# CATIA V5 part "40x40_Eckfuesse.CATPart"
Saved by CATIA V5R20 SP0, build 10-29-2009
Part number: 40x40_Eckfuesse
Nomenclature: P40L_N8_I
Source: Unknown
Bounding box of the stored display mesh (mm): x -20 to 20, y -20 to 20, z -150 to 180
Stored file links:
  C:\Users\Andi\Desktop\Offene Projekte\Plasmacutter\Rahmen\40x40_Eckfuesse.CATPart
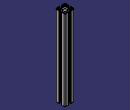
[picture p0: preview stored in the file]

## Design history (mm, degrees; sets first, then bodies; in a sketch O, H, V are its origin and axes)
Set1
  Sketch1 on face of Solid1, origin (0, 0, 150), H (1, 0, 0), V (0, 1, 0)
    projected arc E1 centre (-18.5, 5.5) radius 1.5 from (-20, 5.5) to (-18.5, 4) ccw from edge [face of Solid1 | face of Solid1]
    projected line E2 (-16.5, 4) -> (-18.5, 4) from edge [face of Solid1 | face of Solid1]
    projected arc E3 centre (-16.5, 5) radius 1 from (-16.5, 4) to (-15.5, 5) ccw from edge [face of Solid1 | face of Solid1]
    projected line E4 (-15.5, 6.5) -> (-15.5, 5) from edge [face of Solid1 | face of Solid1]
    projected arc E5 centre (-16, 6.5) radius 0.5 from (-15.5, 6.5) to (-16, 7) ccw from edge [face of Solid1 | face of Solid1]
    projected line E6 (-17.5, 7) -> (-16, 7) from edge [face of Solid1 | face of Solid1]
    projected arc E7 centre (-17.5, 7.5) radius 0.5 from (-18, 7.5) to (-17.5, 7) ccw from edge [face of Solid1 | face of Solid1]
    projected arc E8 centre (-15.5, 7.5) radius 2.5 from (-15.5, 10) to (-18, 7.5) ccw from edge [face of Solid1 | face of Solid1]
    projected line E9 (-14.1924, 10) -> (-15.5, 10) from edge [face of Solid1 | face of Solid1]
    projected arc E10 centre (-14.1924, 5) radius 5 from (-10.6569, 8.5355) to (-14.1924, 10) ccw from edge [face of Solid1 | face of Solid1]
    projected line E11 (-9.2145, 7.0931) -> (-10.6569, 8.5355) from edge [face of Solid1 | face of Solid1]
    projected arc E12 centre (-12.75, 3.5576) radius 5 from (-7.75, 3.5576) to (-9.2145, 7.0931) ccw from edge [face of Solid1 | face of Solid1]
    projected line E13 (-7.75, -3.5576) -> (-7.75, 3.5576) from edge [face of Solid1 | face of Solid1]
    projected arc E14 centre (-12.75, -3.5576) radius 5 from (-9.2145, -7.0931) to (-7.75, -3.5576) ccw from edge [face of Solid1 | face of Solid1]
    projected line E15 (-10.6569, -8.5355) -> (-9.2145, -7.0931) from edge [face of Solid1 | face of Solid1]
    projected arc E16 centre (-14.1924, -5) radius 5 from (-14.1924, -10) to (-10.6569, -8.5355) ccw from edge [face of Solid1 | face of Solid1]
    projected line E17 (-15.5, -10) -> (-14.1924, -10) from edge [face of Solid1 | face of Solid1]
    projected arc E18 centre (-15.5, -7.5) radius 2.5 from (-18, -7.5) to (-15.5, -10) ccw from edge [face of Solid1 | face of Solid1]
    projected arc E19 centre (-17.5, -7.5) radius 0.5 from (-17.5, -7) to (-18, -7.5) ccw from edge [face of Solid1 | face of Solid1]
    projected line E20 (-16, -7) -> (-17.5, -7) from edge [face of Solid1 | face of Solid1]
    projected arc E21 centre (-16, -6.5) radius 0.5 from (-16, -7) to (-15.5, -6.5) ccw from edge [face of Solid1 | face of Solid1]
    projected line E22 (-15.5, -5) -> (-15.5, -6.5) from edge [face of Solid1 | face of Solid1]
    projected arc E23 centre (-16.5, -5) radius 1 from (-15.5, -5) to (-16.5, -4) ccw from edge [face of Solid1 | face of Solid1]
    projected line E24 (-18.5, -4) -> (-16.5, -4) from edge [face of Solid1 | face of Solid1]
    projected arc E25 centre (-18.5, -5.5) radius 1.5 from (-18.5, -4) to (-20, -5.5) ccw from edge [face of Solid1 | face of Solid1]
    projected line E26 (-20, -16) -> (-20, -5.5) from edge [face of Solid1 | face of Solid1]
    projected arc E27 centre (-16, -16) radius 4 from (-20, -16) to (-16, -20) ccw from edge [face of Solid1 | face of Solid1]
    projected line E28 (-5.5, -20) -> (-16, -20) from edge [face of Solid1 | face of Solid1]
    projected arc E29 centre (-5.5, -18.5) radius 1.5 from (-5.5, -20) to (-4, -18.5) ccw from edge [face of Solid1 | face of Solid1]
    projected line E30 (-4, -16.5) -> (-4, -18.5) from edge [face of Solid1 | face of Solid1]
    projected arc E31 centre (-5, -16.5) radius 1 from (-4, -16.5) to (-5, -15.5) ccw from edge [face of Solid1 | face of Solid1]
    projected line E32 (-6.5, -15.5) -> (-5, -15.5) from edge [face of Solid1 | face of Solid1]
    projected arc E33 centre (-6.5, -16) radius 0.5 from (-6.5, -15.5) to (-7, -16) ccw from edge [face of Solid1 | face of Solid1]
    projected line E34 (-7, -17.5) -> (-7, -16) from edge [face of Solid1 | face of Solid1]
    projected arc E35 centre (-7.5, -17.5) radius 0.5 from (-7.5, -18) to (-7, -17.5) ccw from edge [face of Solid1 | face of Solid1]
    projected arc E36 centre (-7.5, -15.5) radius 2.5 from (-10, -15.5) to (-7.5, -18) ccw from edge [face of Solid1 | face of Solid1]
    projected line E37 (-10, -14.1924) -> (-10, -15.5) from edge [face of Solid1 | face of Solid1]
    projected arc E38 centre (-5, -14.1924) radius 5 from (-8.5355, -10.6569) to (-10, -14.1924) ccw from edge [face of Solid1 | face of Solid1]
    projected line E39 (-7.0931, -9.2145) -> (-8.5355, -10.6569) from edge [face of Solid1 | face of Solid1]
    projected arc E40 centre (-3.5576, -12.75) radius 5 from (-3.5576, -7.75) to (-7.0931, -9.2145) ccw from edge [face of Solid1 | face of Solid1]
    projected line E41 (3.5576, -7.75) -> (-3.5576, -7.75) from edge [face of Solid1 | face of Solid1]
    projected arc E42 centre (3.5576, -12.75) radius 5 from (7.0931, -9.2145) to (3.5576, -7.75) ccw from edge [face of Solid1 | face of Solid1]
    projected line E43 (8.5355, -10.6569) -> (7.0931, -9.2145) from edge [face of Solid1 | face of Solid1]
    projected arc E44 centre (5, -14.1924) radius 5 from (10, -14.1924) to (8.5355, -10.6569) ccw from edge [face of Solid1 | face of Solid1]
    projected line E45 (10, -15.5) -> (10, -14.1924) from edge [face of Solid1 | face of Solid1]
    projected arc E46 centre (7.5, -15.5) radius 2.5 from (7.5, -18) to (10, -15.5) ccw from edge [face of Solid1 | face of Solid1]
    projected arc E47 centre (7.5, -17.5) radius 0.5 from (7, -17.5) to (7.5, -18) ccw from edge [face of Solid1 | face of Solid1]
    projected line E48 (7, -16) -> (7, -17.5) from edge [face of Solid1 | face of Solid1]
    projected arc E49 centre (6.5, -16) radius 0.5 from (7, -16) to (6.5, -15.5) ccw from edge [face of Solid1 | face of Solid1]
    projected line E50 (5, -15.5) -> (6.5, -15.5) from edge [face of Solid1 | face of Solid1]
    projected arc E51 centre (5, -16.5) radius 1 from (5, -15.5) to (4, -16.5) ccw from edge [face of Solid1 | face of Solid1]
    projected line E52 (4, -18.5) -> (4, -16.5) from edge [face of Solid1 | face of Solid1]
    projected arc E53 centre (5.5, -18.5) radius 1.5 from (4, -18.5) to (5.5, -20) ccw from edge [face of Solid1 | face of Solid1]
    projected line E54 (16, -20) -> (5.5, -20) from edge [face of Solid1 | face of Solid1]
    projected arc E55 centre (16, -16) radius 4 from (16, -20) to (20, -16) ccw from edge [face of Solid1 | face of Solid1]
    projected line E56 (20, -5.5) -> (20, -16) from edge [face of Solid1 | face of Solid1]
    projected arc E57 centre (18.5, -5.5) radius 1.5 from (20, -5.5) to (18.5, -4) ccw from edge [face of Solid1 | face of Solid1]
    projected line E58 (16.5, -4) -> (18.5, -4) from edge [face of Solid1 | face of Solid1]
    projected arc E59 centre (16.5, -5) radius 1 from (16.5, -4) to (15.5, -5) ccw from edge [face of Solid1 | face of Solid1]
    projected line E60 (15.5, -6.5) -> (15.5, -5) from edge [face of Solid1 | face of Solid1]
    projected arc E61 centre (16, -6.5) radius 0.5 from (15.5, -6.5) to (16, -7) ccw from edge [face of Solid1 | face of Solid1]
    projected line E62 (17.5, -7) -> (16, -7) from edge [face of Solid1 | face of Solid1]
    projected arc E63 centre (17.5, -7.5) radius 0.5 from (18, -7.5) to (17.5, -7) ccw from edge [face of Solid1 | face of Solid1]
    projected arc E64 centre (15.5, -7.5) radius 2.5 from (15.5, -10) to (18, -7.5) ccw from edge [face of Solid1 | face of Solid1]
    projected line E65 (14.1924, -10) -> (15.5, -10) from edge [face of Solid1 | face of Solid1]
    projected arc E66 centre (14.1924, -5) radius 5 from (10.6569, -8.5355) to (14.1924, -10) ccw from edge [face of Solid1 | face of Solid1]
    projected line E67 (9.2145, -7.0931) -> (10.6569, -8.5355) from edge [face of Solid1 | face of Solid1]
    projected arc E68 centre (12.75, -3.5576) radius 5 from (7.75, -3.5576) to (9.2145, -7.0931) ccw from edge [face of Solid1 | face of Solid1]
    projected line E69 (7.75, 3.5576) -> (7.75, -3.5576) from edge [face of Solid1 | face of Solid1]
    projected arc E70 centre (12.75, 3.5576) radius 5 from (9.2145, 7.0931) to (7.75, 3.5576) ccw from edge [face of Solid1 | face of Solid1]
    projected line E71 (10.6569, 8.5355) -> (9.2145, 7.0931) from edge [face of Solid1 | face of Solid1]
    projected arc E72 centre (14.1924, 5) radius 5 from (14.1924, 10) to (10.6569, 8.5355) ccw from edge [face of Solid1 | face of Solid1]
    projected line E73 (15.5, 10) -> (14.1924, 10) from edge [face of Solid1 | face of Solid1]
    projected arc E74 centre (15.5, 7.5) radius 2.5 from (18, 7.5) to (15.5, 10) ccw from edge [face of Solid1 | face of Solid1]
    projected arc E75 centre (17.5, 7.5) radius 0.5 from (17.5, 7) to (18, 7.5) ccw from edge [face of Solid1 | face of Solid1]
    projected line E76 (16, 7) -> (17.5, 7) from edge [face of Solid1 | face of Solid1]
    projected arc E77 centre (16, 6.5) radius 0.5 from (16, 7) to (15.5, 6.5) ccw from edge [face of Solid1 | face of Solid1]
    projected line E78 (15.5, 5) -> (15.5, 6.5) from edge [face of Solid1 | face of Solid1]
    projected arc E79 centre (16.5, 5) radius 1 from (15.5, 5) to (16.5, 4) ccw from edge [face of Solid1 | face of Solid1]
    projected line E80 (18.5, 4) -> (16.5, 4) from edge [face of Solid1 | face of Solid1]
    projected arc E81 centre (18.5, 5.5) radius 1.5 from (18.5, 4) to (20, 5.5) ccw from edge [face of Solid1 | face of Solid1]
    projected line E82 (20, 16) -> (20, 5.5) from edge [face of Solid1 | face of Solid1]
    projected arc E83 centre (16, 16) radius 4 from (20, 16) to (16, 20) ccw from edge [face of Solid1 | face of Solid1]
    projected line E84 (5.5, 20) -> (16, 20) from edge [face of Solid1 | face of Solid1]
    projected arc E85 centre (5.5, 18.5) radius 1.5 from (5.5, 20) to (4, 18.5) ccw from edge [face of Solid1 | face of Solid1]
    projected line E86 (4, 16.5) -> (4, 18.5) from edge [face of Solid1 | face of Solid1]
    projected arc E87 centre (5, 16.5) radius 1 from (4, 16.5) to (5, 15.5) ccw from edge [face of Solid1 | face of Solid1]
    projected line E88 (6.5, 15.5) -> (5, 15.5) from edge [face of Solid1 | face of Solid1]
    projected arc E89 centre (6.5, 16) radius 0.5 from (6.5, 15.5) to (7, 16) ccw from edge [face of Solid1 | face of Solid1]
    projected line E90 (7, 17.5) -> (7, 16) from edge [face of Solid1 | face of Solid1]
    projected arc E91 centre (7.5, 17.5) radius 0.5 from (7.5, 18) to (7, 17.5) ccw from edge [face of Solid1 | face of Solid1]
    projected arc E92 centre (7.5, 15.5) radius 2.5 from (10, 15.5) to (7.5, 18) ccw from edge [face of Solid1 | face of Solid1]
    projected line E93 (10, 14.1924) -> (10, 15.5) from edge [face of Solid1 | face of Solid1]
    projected arc E94 centre (5, 14.1924) radius 5 from (8.5355, 10.6569) to (10, 14.1924) ccw from edge [face of Solid1 | face of Solid1]
    projected line E95 (7.0931, 9.2145) -> (8.5355, 10.6569) from edge [face of Solid1 | face of Solid1]
    projected arc E96 centre (3.5576, 12.75) radius 5 from (3.5576, 7.75) to (7.0931, 9.2145) ccw from edge [face of Solid1 | face of Solid1]
    projected line E97 (-3.5576, 7.75) -> (3.5576, 7.75) from edge [face of Solid1 | face of Solid1]
    projected arc E98 centre (-3.5576, 12.75) radius 5 from (-7.0931, 9.2145) to (-3.5576, 7.75) ccw from edge [face of Solid1 | face of Solid1]
    projected line E99 (-8.5355, 10.6569) -> (-7.0931, 9.2145) from edge [face of Solid1 | face of Solid1]
    projected arc E100 centre (-5, 14.1924) radius 5 from (-10, 14.1924) to (-8.5355, 10.6569) ccw from edge [face of Solid1 | face of Solid1]
    projected line E101 (-10, 15.5) -> (-10, 14.1924) from edge [face of Solid1 | face of Solid1]
    projected arc E102 centre (-7.5, 15.5) radius 2.5 from (-7.5, 18) to (-10, 15.5) ccw from edge [face of Solid1 | face of Solid1]
    projected arc E103 centre (-7.5, 17.5) radius 0.5 from (-7, 17.5) to (-7.5, 18) ccw from edge [face of Solid1 | face of Solid1]
    projected line E104 (-7, 16) -> (-7, 17.5) from edge [face of Solid1 | face of Solid1]
    projected arc E105 centre (-6.5, 16) radius 0.5 from (-7, 16) to (-6.5, 15.5) ccw from edge [face of Solid1 | face of Solid1]
    projected line E106 (-5, 15.5) -> (-6.5, 15.5) from edge [face of Solid1 | face of Solid1]
    projected arc E107 centre (-5, 16.5) radius 1 from (-5, 15.5) to (-4, 16.5) ccw from edge [face of Solid1 | face of Solid1]
    projected line E108 (-4, 18.5) -> (-4, 16.5) from edge [face of Solid1 | face of Solid1]
    projected arc E109 centre (-5.5, 18.5) radius 1.5 from (-4, 18.5) to (-5.5, 20) ccw from edge [face of Solid1 | face of Solid1]
    projected line E110 (-16, 20) -> (-5.5, 20) from edge [face of Solid1 | face of Solid1]
    projected arc E111 centre (-16, 16) radius 4 from (-16, 20) to (-20, 16) ccw from edge [face of Solid1 | face of Solid1]
    projected line E112 (-20, 5.5) -> (-20, 16) from edge [face of Solid1 | face of Solid1]
    projected line E113 (11.8, -17.7) -> (11.8, -12.3) from edge [face of Solid1 | face of Solid1]
    projected arc E114 centre (12.3, -12.3) radius 0.5 from (12.3, -11.8) to (11.8, -12.3) ccw from edge [face of Solid1 | face of Solid1]
    projected line E115 (12.3, -11.8) -> (17.7, -11.8) from edge [face of Solid1 | face of Solid1]
    projected arc E116 centre (17.7, -12.3) radius 0.5 from (18.2, -12.3) to (17.7, -11.8) ccw from edge [face of Solid1 | face of Solid1]
    projected line E117 (18.2, -12.3) -> (18.2, -16) from edge [face of Solid1 | face of Solid1]
    projected arc E118 centre (16, -16) radius 2.2 from (16, -18.2) to (18.2, -16) ccw from edge [face of Solid1 | face of Solid1]
    projected line E119 (16, -18.2) -> (12.3, -18.2) from edge [face of Solid1 | face of Solid1]
    projected arc E120 centre (12.3, -17.7) radius 0.5 from (11.8, -17.7) to (12.3, -18.2) ccw from edge [face of Solid1 | face of Solid1]
    projected line E121 (-17.7, -11.8) -> (-12.3, -11.8) from edge [face of Solid1 | face of Solid1]
    projected arc E122 centre (-12.3, -12.3) radius 0.5 from (-11.8, -12.3) to (-12.3, -11.8) ccw from edge [face of Solid1 | face of Solid1]
    projected line E123 (-11.8, -12.3) -> (-11.8, -17.7) from edge [face of Solid1 | face of Solid1]
    projected arc E124 centre (-12.3, -17.7) radius 0.5 from (-12.3, -18.2) to (-11.8, -17.7) ccw from edge [face of Solid1 | face of Solid1]
    projected line E125 (-12.3, -18.2) -> (-16, -18.2) from edge [face of Solid1 | face of Solid1]
    projected arc E126 centre (-16, -16) radius 2.2 from (-18.2, -16) to (-16, -18.2) ccw from edge [face of Solid1 | face of Solid1]
    projected line E127 (-18.2, -16) -> (-18.2, -12.3) from edge [face of Solid1 | face of Solid1]
    projected arc E128 centre (-17.7, -12.3) radius 0.5 from (-17.7, -11.8) to (-18.2, -12.3) ccw from edge [face of Solid1 | face of Solid1]
    projected line E129 (-11.8, 17.7) -> (-11.8, 12.3) from edge [face of Solid1 | face of Solid1]
    projected arc E130 centre (-12.3, 12.3) radius 0.5 from (-12.3, 11.8) to (-11.8, 12.3) ccw from edge [face of Solid1 | face of Solid1]
    projected line E131 (-12.3, 11.8) -> (-17.7, 11.8) from edge [face of Solid1 | face of Solid1]
    projected arc E132 centre (-17.7, 12.3) radius 0.5 from (-18.2, 12.3) to (-17.7, 11.8) ccw from edge [face of Solid1 | face of Solid1]
    projected line E133 (-18.2, 12.3) -> (-18.2, 16) from edge [face of Solid1 | face of Solid1]
    projected arc E134 centre (-16, 16) radius 2.2 from (-16, 18.2) to (-18.2, 16) ccw from edge [face of Solid1 | face of Solid1]
    projected line E135 (-16, 18.2) -> (-12.3, 18.2) from edge [face of Solid1 | face of Solid1]
    projected arc E136 centre (-12.3, 17.7) radius 0.5 from (-11.8, 17.7) to (-12.3, 18.2) ccw from edge [face of Solid1 | face of Solid1]
    projected line E137 (17.7, 11.8) -> (12.3, 11.8) from edge [face of Solid1 | face of Solid1]
    projected arc E138 centre (12.3, 12.3) radius 0.5 from (11.8, 12.3) to (12.3, 11.8) ccw from edge [face of Solid1 | face of Solid1]
    projected line E139 (11.8, 12.3) -> (11.8, 17.7) from edge [face of Solid1 | face of Solid1]
    projected arc E140 centre (12.3, 17.7) radius 0.5 from (12.3, 18.2) to (11.8, 17.7) ccw from edge [face of Solid1 | face of Solid1]
    projected line E141 (12.3, 18.2) -> (16, 18.2) from edge [face of Solid1 | face of Solid1]
    projected arc E142 centre (16, 16) radius 2.2 from (18.2, 16) to (16, 18.2) ccw from edge [face of Solid1 | face of Solid1]
    projected line E143 (18.2, 16) -> (18.2, 12.3) from edge [face of Solid1 | face of Solid1]
    projected arc E144 centre (17.7, 12.3) radius 0.5 from (17.7, 11.8) to (18.2, 12.3) ccw from edge [face of Solid1 | face of Solid1]
    projected arc E145 centre (0, 0) radius 3.4 from (-3.4, 0) to (3.4, 0) ccw from edge [face of Solid1 | face of Solid1]
    projected arc E146 centre (0, 0) radius 3.4 from (3.4, 0) to (-3.4, 0) ccw from edge [face of Solid1 | face of Solid1]
Body1 "MANIFOLD_SOLID_BREP #5039" (main body)
  Solid1: solid without history
  Pad1: profile Sketch1, direction (0, 0, 1), length 30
